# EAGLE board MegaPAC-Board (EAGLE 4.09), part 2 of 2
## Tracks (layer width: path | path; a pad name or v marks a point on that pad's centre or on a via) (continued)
S$583  (via drill 0.81 pad 1.78)
  other vias: 55.88,15.24
S$584  (via drill 0.81 pad 1.78)
  other vias: 55.88,12.7
S$585  (via drill 0.81 pad 1.78)
  other vias: 55.88,10.16
S$586
  Bottom 1.676: 62.87,25.72 45.4,25.72 45.4,40.01
S$587  (via drill 0.81 pad 1.78)
  other vias: 17.78,88.9
S$588  (via drill 0.81 pad 1.78)
  other vias: 53.34,10.16
S$589  (via drill 0.81 pad 1.78)
  other vias: 53.34,12.7
S$590  (via drill 0.81 pad 1.78)
  other vias: 53.34,15.24
S$591  (via drill 0.81 pad 1.78)
  other vias: 50.8,15.24
S$592  (via drill 0.81 pad 1.78)
  other vias: 50.8,12.7
S$593  (via drill 0.81 pad 1.78)
  other vias: 50.8,10.16
S$594  (via drill 0.81 pad 1.78)
  other vias: 50.8,7.62
S$595  (via drill 0.81 pad 1.78)
  other vias: 48.26,7.62
S$596  (via drill 0.81 pad 1.78)
  other vias: 48.26,10.16
S$597  (via drill 0.81 pad 1.78)
  other vias: 48.26,12.7
S$598  (via drill 0.81 pad 1.78)
  other vias: 48.26,15.24
S$599  (via drill 0.81 pad 1.78)
  other vias: 45.72,15.24
S$600  (via drill 0.81 pad 1.78)
  other vias: 45.72,12.7
S$601  (via drill 0.81 pad 1.78)
  other vias: 45.72,10.16
S$602  (via drill 0.81 pad 1.78)
  other vias: 45.72,7.62
S$603  (via drill 0.81 pad 1.78)
  other vias: 38.1,40.64
S$604  (via drill 0.81 pad 1.78)
  other vias: 38.1,38.1
S$605  (via drill 0.81 pad 1.78)
  other vias: 35.56,38.1
S$606  (via drill 0.81 pad 1.78)
  other vias: 33.02,38.1
S$607  (via drill 0.81 pad 1.78)
  other vias: 33.02,35.56
S$608  (via drill 0.81 pad 1.78)
  other vias: 35.56,35.56
S$609  (via drill 0.81 pad 1.78)
  other vias: 38.1,35.56
S$610  (via drill 0.81 pad 1.78)
  other vias: 38.1,33.02
S$611  (via drill 0.81 pad 1.78)
  other vias: 38.1,30.48
S$612  (via drill 0.81 pad 1.78)
  other vias: 38.1,27.94
S$613  (via drill 0.81 pad 1.78)
  other vias: 38.1,25.4
S$614  (via drill 0.81 pad 1.78)
  other vias: 35.56,25.4
S$615  (via drill 0.81 pad 1.78)
  other vias: 35.56,27.94
S$616  (via drill 0.81 pad 1.78)
  other vias: 35.56,30.48
S$617  (via drill 0.81 pad 1.78)
  other vias: 35.56,33.02
S$618  (via drill 0.81 pad 1.78)
  other vias: 33.02,33.02
S$619  (via drill 0.81 pad 1.78)
  other vias: 33.02,30.48
S$620  (via drill 0.81 pad 1.78)
  other vias: 33.02,27.94
S$621  (via drill 0.81 pad 1.78)
  other vias: 33.02,25.4
S$622  (via drill 0.81 pad 1.78)
  other vias: 33.02,22.86
S$623  (via drill 0.81 pad 1.78)
  other vias: 35.56,22.86
S$624  (via drill 0.81 pad 1.78)
  other vias: 38.1,22.86
S$625  (via drill 0.81 pad 1.78)
  other vias: 38.1,20.32
S$626  (via drill 0.81 pad 1.78)
  other vias: 35.56,20.32
S$627  (via drill 0.81 pad 1.78)
  other vias: 33.02,20.32
S$628  (via drill 0.81 pad 1.78)
  other vias: 33.02,17.78
S$629  (via drill 0.81 pad 1.78)
  other vias: 35.56,17.78
S$630  (via drill 0.81 pad 1.78)
  other vias: 38.1,17.78
S$631  (via drill 0.81 pad 1.78)
  other vias: 38.1,15.24
S$632  (via drill 0.81 pad 1.78)
  other vias: 38.1,12.7
S$633  (via drill 0.81 pad 1.78)
  other vias: 38.1,10.16
S$634  (via drill 0.81 pad 1.78)
  other vias: 38.1,7.62
S$635  (via drill 0.81 pad 1.78)
  other vias: 35.56,7.62
S$636  (via drill 0.81 pad 1.78)
  other vias: 35.56,10.16
S$637  (via drill 0.81 pad 1.78)
  other vias: 35.56,12.7
S$638  (via drill 0.81 pad 1.78)
  other vias: 35.56,15.24
S$639  (via drill 0.81 pad 1.78)
  other vias: 33.02,15.24
S$640  (via drill 0.81 pad 1.78)
  other vias: 33.02,12.7
S$641  (via drill 0.81 pad 1.78)
  other vias: 33.02,10.16
S$642  (via drill 0.81 pad 1.78)
  other vias: 33.02,7.62
S$643  (via drill 0.81 pad 1.78)
  other vias: 68.58,22.86
S$644  (via drill 0.81 pad 1.78)
  other vias: 71.12,22.86
S$645  (via drill 0.81 pad 1.78)
  other vias: 73.66,22.86
S$646  (via drill 0.81 pad 1.78)
  other vias: 73.66,20.32
S$647  (via drill 0.81 pad 1.78)
  other vias: 71.12,20.32
S$648  (via drill 0.81 pad 1.78)
  other vias: 68.58,20.32
S$649  (via drill 0.81 pad 1.78)
  other vias: 68.58,17.78
S$650  (via drill 0.81 pad 1.78)
  other vias: 71.12,17.78
S$651  (via drill 0.81 pad 1.78)
  other vias: 73.66,17.78
S$652  (via drill 0.81 pad 1.78)
  other vias: 73.66,15.24
S$653  (via drill 0.81 pad 1.78)
  other vias: 73.66,12.7
S$654  (via drill 0.81 pad 1.78)
  other vias: 73.66,10.16
S$655  (via drill 0.81 pad 1.78)
  other vias: 73.66,7.62
S$656  (via drill 0.81 pad 1.78)
  other vias: 71.12,7.62
S$658  (via drill 0.81 pad 1.78)
  other vias: 71.12,10.16
S$659  (via drill 0.81 pad 1.78)
  other vias: 71.12,12.7
S$660  (via drill 0.81 pad 1.78)
  other vias: 71.12,15.24
S$661  (via drill 0.81 pad 1.78)
  other vias: 68.58,15.24
S$662  (via drill 0.81 pad 1.78)
  other vias: 68.58,12.7
S$663  (via drill 0.81 pad 1.78)
  other vias: 68.58,10.16
S$664  (via drill 0.81 pad 1.78)
  other vias: 68.58,7.62
S$665  (via drill 0.81 pad 1.78)
  other vias: 139.7,22.86
S$666  (via drill 0.81 pad 1.78)
  other vias: 142.24,22.86
S$667  (via drill 0.81 pad 1.78)
  other vias: 144.78,22.86
S$668  (via drill 0.81 pad 1.78)
  other vias: 144.78,20.32
S$669  (via drill 0.81 pad 1.78)
  other vias: 142.24,20.32
S$670  (via drill 0.81 pad 1.78)
  other vias: 139.7,20.32
S$671  (via drill 0.81 pad 1.78)
  other vias: 139.7,17.78
S$672  (via drill 0.81 pad 1.78)
  other vias: 142.24,17.78
S$674  (via drill 0.81 pad 1.78)
  other vias: 144.78,17.78
S$675  (via drill 0.81 pad 1.78)
  other vias: 144.78,15.24
S$676  (via drill 0.81 pad 1.78)
  other vias: 144.78,12.7
S$677  (via drill 0.81 pad 1.78)
  other vias: 144.78,10.16
S$678
  Bottom 1.778: 132.08,17.78 134.62,17.78
S$679
  Bottom 1.778: 132.08,20.32 134.62,20.32
S$680  (via drill 0.81 pad 1.78)
  other vias: 142.24,10.16
S$681  (via drill 0.81 pad 1.78)
  other vias: 142.24,12.7
S$682  (via drill 0.81 pad 1.78)
  other vias: 142.24,15.24
S$683  (via drill 0.81 pad 1.78)
  other vias: 139.7,15.24
S$684  (via drill 0.81 pad 1.78)
  other vias: 139.7,12.7
S$685  (via drill 0.81 pad 1.78)
  other vias: 139.7,10.16
S$686
  Bottom 1.676: 21.59,39.37 K1.P$2
S$687  (via drill 0.81 pad 1.78)
  other vias: 147.32,22.86
S$688  (via drill 0.81 pad 1.78)
  other vias: 149.86,22.86
S$689  (via drill 0.81 pad 1.78)
  other vias: 152.4,22.86
S$690  (via drill 0.81 pad 1.78)
  other vias: 152.4,20.32
S$691  (via drill 0.81 pad 1.78)
  other vias: 149.86,20.32
S$692  (via drill 0.81 pad 1.78)
  other vias: 147.32,20.32
S$694  (via drill 0.81 pad 1.78)
  other vias: 147.32,17.78
S$695  (via drill 0.81 pad 1.78)
  other vias: 149.86,17.78
S$696  (via drill 0.81 pad 1.78)
  other vias: 152.4,17.78
S$697  (via drill 0.81 pad 1.78)
  other vias: 147.32,15.24
S$698  (via drill 0.81 pad 1.78)
  other vias: 149.86,15.24
S$699  (via drill 0.81 pad 1.78)
  other vias: 152.4,15.24
S$700  (via drill 0.81 pad 1.78)
  other vias: 154.94,22.86
S$701  (via drill 0.81 pad 1.78)
  other vias: 154.94,20.32
S$702  (via drill 0.81 pad 1.78)
  other vias: 154.94,17.78
S$703  (via drill 0.81 pad 1.78)
  other vias: 154.94,15.24
S$704
  Bottom 1.778: 132.08,15.24 134.62,15.24
S$705
  Bottom 2.54: 135.89,78.74 153.67,78.74
S$706
  Bottom 1.422: H5.K 120.65,93.03 120.65,90.17
  Bottom 1.676: H5.K 119.7,94.3 | 120.65,90.17 123.19,90.17 | 118.43,85.72 118.43,87.63
  Bottom 1.778: 131.44,80.01 131.44,89.22 | 132.72,79.38 132.72,89.85 128.59,89.85 | 120.02,90.17 120.65,90.17 117.47,90.17 117.47,87.63 118.43,87.63
  Bottom 1.93: 131.44,80.01 128.59,80.01 128.59,89.85 128.59,90.17 123.19,90.17 | 120.65,90.17 120.65,87.63 118.43,87.63
S$707
  Bottom 1.676: 135.89,80.01 135.89,80.33 | 135.89,80.01 135.89,79.38 | 135.89,80.01 135.57,80.33 136.21,80.33 136.21,79.69 135.57,79.69
S$709
  Bottom 1.676: 21.59,22.86 K2.P$2
S$710  (via drill 0.81 pad 1.78)  (4 unrouted)
  other vias: 142.24,5.08 139.7,5.08 139.7,2.54 142.24,2.54 144.78,2.54
S$711  (via drill 0.81 pad 1.78)
  other vias: 144.78,5.08
S$712  (via drill 0.81 pad 1.78)
  other vias: 129.54,22.86
S$713  (via drill 0.81 pad 1.78)
  other vias: 129.54,20.32
S$714  (via drill 0.81 pad 1.78)
  other vias: 129.54,17.78
S$715  (via drill 0.81 pad 1.78)
  other vias: 15.24,88.9
S$716  (via drill 0.81 pad 1.78)
  other vias: 12.7,88.9
S$717  (via drill 0.81 pad 1.78)
  other vias: 12.7,91.44
S$718  (via drill 0.81 pad 1.78)
  other vias: 15.24,91.44
S$719  (via drill 0.81 pad 1.78)
  other vias: 129.54,25.4
S$720  (via drill 0.81 pad 1.78)
  other vias: 127,25.4
S$721  (via drill 0.81 pad 1.78)
  other vias: 124.46,25.4
S$722  (via drill 0.81 pad 1.78)
  other vias: 121.92,25.4
S$723  (via drill 0.81 pad 1.78)
  other vias: 119.38,25.4
S$724  (via drill 0.81 pad 1.78)
  other vias: 116.84,25.4
S$725  (via drill 0.81 pad 1.78)
  other vias: 114.3,25.4
S$726  (via drill 0.81 pad 1.78)
  other vias: 111.76,25.4
S$727  (via drill 0.81 pad 1.78)
  other vias: 109.22,25.4
S$728  (via drill 0.81 pad 1.78)
  other vias: 106.68,25.4
S$729  (via drill 0.81 pad 1.78)
  other vias: 104.14,25.4
S$730  (via drill 0.81 pad 1.78)
  other vias: 101.6,25.4
S$731  (via drill 0.81 pad 1.78)
  other vias: 99.06,25.4
S$732  (via drill 0.81 pad 1.78)
  other vias: 96.52,25.4
S$733  (via drill 0.81 pad 1.78)
  other vias: 93.98,25.4
S$734  (via drill 0.81 pad 1.78)
  other vias: 91.44,25.4
S$735  (via drill 0.81 pad 1.78)
  other vias: 88.9,25.4
S$736  (via drill 0.81 pad 1.78)
  other vias: 86.36,25.4
S$737  (via drill 0.81 pad 1.78)
  other vias: 83.82,25.4
S$738  (via drill 0.81 pad 1.78)
  other vias: 68.58,5.08
S$739  (via drill 0.81 pad 1.78)
  other vias: 71.12,5.08
S$740  (via drill 0.81 pad 1.78)
  other vias: 73.66,5.08
S$741  (via drill 0.81 pad 1.78)
  other vias: 76.2,5.08
S$742  (via drill 0.81 pad 1.78)
  other vias: 78.74,5.08
S$743  (via drill 0.81 pad 1.78)
  other vias: 81.28,5.08
S$744  (via drill 0.81 pad 1.78)
  other vias: 83.82,5.08
S$745  (via drill 0.81 pad 1.78)
  other vias: 86.36,5.08
S$746  (via drill 0.81 pad 1.78)
  other vias: 88.9,5.08
S$747  (via drill 0.81 pad 1.78)
  other vias: 91.44,5.08
S$748  (via drill 0.81 pad 1.78)
  other vias: 93.98,5.08
S$749  (via drill 0.81 pad 1.78)
  other vias: 96.52,5.08
S$750  (via drill 0.81 pad 1.78)
  other vias: 99.06,5.08
S$751  (via drill 0.81 pad 1.78)
  other vias: 101.6,5.08
S$752  (via drill 0.81 pad 1.78)
  other vias: 104.14,5.08
S$753  (via drill 0.81 pad 1.78)
  other vias: 106.68,5.08
S$754  (via drill 0.81 pad 1.78)
  other vias: 109.22,5.08
S$755  (via drill 0.81 pad 1.78)
  other vias: 111.76,5.08
S$756  (via drill 0.81 pad 1.78)
  other vias: 114.3,5.08
S$757  (via drill 0.81 pad 1.78)
  other vias: 116.84,5.08
S$758  (via drill 0.81 pad 1.78)
  other vias: 119.38,5.08
S$759  (via drill 0.81 pad 1.78)
  other vias: 121.92,5.08
S$760  (via drill 0.81 pad 1.78)
  other vias: 124.46,5.08
S$761  (via drill 0.81 pad 1.78)
  other vias: 127,5.08
S$762  (via drill 0.81 pad 1.78)
  other vias: 17.78,91.44
S$763  (via drill 0.81 pad 1.78)
  other vias: 66.04,22.86
S$764  (via drill 0.81 pad 1.78)
  other vias: 66.04,20.32
S$765  (via drill 0.81 pad 1.78)
  other vias: 66.04,17.78
S$766  (via drill 0.81 pad 1.78)
  other vias: 66.04,15.24
S$767  (via drill 0.81 pad 1.78)
  other vias: 66.04,12.7
S$768  (via drill 0.81 pad 1.78)
  other vias: 66.04,10.16
S$769  (via drill 0.81 pad 1.78)
  other vias: 66.04,7.62
S$770  (via drill 0.81 pad 1.78)
  other vias: 66.04,5.08
S$771  (via drill 0.81 pad 1.78)
  other vias: 17.78,93.98
S$772  (via drill 0.81 pad 1.78)
  other vias: 15.24,93.98
S$773  (via drill 0.81 pad 1.78)
  other vias: 50.8,5.08
S$774  (via drill 0.81 pad 1.78)
  other vias: 48.26,5.08
S$775  (via drill 0.81 pad 1.78)
  other vias: 45.72,5.08
S$776  (via drill 0.81 pad 1.78)
  other vias: 43.18,5.08
S$777  (via drill 0.81 pad 1.78)
  other vias: 43.18,7.62
S$778  (via drill 0.81 pad 1.78)
  other vias: 43.18,10.16
S$779  (via drill 0.81 pad 1.78)
  other vias: 43.18,12.7
S$780  (via drill 0.81 pad 1.78)
  other vias: 43.18,15.24
S$781  (via drill 0.81 pad 1.78)
  other vias: 43.18,17.78
S$782  (via drill 0.81 pad 1.78)
  other vias: 43.18,20.32
S$783  (via drill 0.81 pad 1.78)
  other vias: 43.18,22.86
S$784  (via drill 0.81 pad 1.78)
  other vias: 40.64,22.86
S$785  (via drill 0.81 pad 1.78)
  other vias: 40.64,20.32
S$786  (via drill 0.81 pad 1.78)
  other vias: 40.64,17.78
S$787  (via drill 0.81 pad 1.78)
  other vias: 40.64,15.24
S$788  (via drill 0.81 pad 1.78)
  other vias: 40.64,12.7
S$789  (via drill 0.81 pad 1.78)
  other vias: 40.64,10.16
S$790  (via drill 0.81 pad 1.78)
  other vias: 40.64,7.62
S$791  (via drill 0.81 pad 1.78)
  other vias: 40.64,5.08
S$792  (via drill 0.81 pad 1.78)
  other vias: 38.1,5.08
S$793  (via drill 0.81 pad 1.78)
  other vias: 35.56,5.08
S$794  (via drill 0.81 pad 1.78)
  other vias: 33.02,5.08
S$795  (via drill 0.81 pad 1.78)
  other vias: 12.7,93.98
S$796  (via drill 0.81 pad 1.78)
  other vias: 12.7,96.52
S$797  (via drill 0.81 pad 1.78)
  other vias: 15.24,96.52
S$798  (via drill 0.81 pad 1.78)
  other vias: 17.78,96.52
S$799  (via drill 0.81 pad 1.78)
  other vias: 17.78,50.8
S$800  (via drill 0.81 pad 1.78)
  other vias: 15.24,50.8
S$801  (via drill 0.81 pad 1.78)
  other vias: 12.7,50.8
S$802  (via drill 0.81 pad 1.78)
  other vias: 10.16,50.8
S$803  (via drill 0.81 pad 1.78)
  other vias: 7.62,50.8
S$804  (via drill 0.81 pad 1.78)
  other vias: 5.08,50.8
S$805  (via drill 0.81 pad 1.78)
  other vias: 2.54,50.8
S$806  (via drill 0.81 pad 1.78)
  other vias: 2.54,48.26
S$807  (via drill 0.81 pad 1.78)
  other vias: 5.08,48.26
S$808  (via drill 0.81 pad 1.78)
  other vias: 7.62,48.26
S$809  (via drill 0.81 pad 1.78)
  other vias: 10.16,48.26
S$810  (via drill 0.81 pad 1.78)
  other vias: 12.7,48.26
S$811  (via drill 0.81 pad 1.78)
  other vias: 15.24,48.26
S$812  (via drill 0.81 pad 1.78)
  other vias: 17.78,48.26
S$813  (via drill 0.81 pad 1.78)
  other vias: 17.78,45.72
S$814  (via drill 0.81 pad 1.78)
  other vias: 15.24,45.72
S$815  (via drill 0.81 pad 1.78)
  other vias: 12.7,45.72
S$816  (via drill 0.81 pad 1.78)
  other vias: 10.16,45.72
S$817  (via drill 0.81 pad 1.78)
  other vias: 7.62,45.72
S$818  (via drill 0.81 pad 1.78)
  other vias: 5.08,45.72
S$819  (via drill 0.81 pad 1.78)
  other vias: 2.54,45.72
S$820  (via drill 0.81 pad 1.78)
  other vias: 30.48,40.64
S$821  (via drill 0.81 pad 1.78)
  other vias: 30.48,33.02
S$822  (via drill 0.81 pad 1.78)
  other vias: 30.8,22.86
S$823  (via drill 0.81 pad 1.78)
  other vias: 30.8,15.24
S$824  (via drill 0.81 pad 1.78)
  other vias: 40.64,40.64
S$825  (via drill 0.81 pad 1.78)
  other vias: 40.64,43.18
S$826  (via drill 0.81 pad 1.78)
  other vias: 40.64,45.72
S$827  (via drill 0.81 pad 1.78)
  other vias: 40.64,48.26
S$828  (via drill 0.81 pad 1.78)
  other vias: 40.64,50.8
S$829  (via drill 0.81 pad 1.78)
  other vias: 40.64,53.34
S$830  (via drill 0.81 pad 1.78)
  other vias: 40.64,55.88
S$831  (via drill 0.81 pad 1.78)
  other vias: 40.64,58.42
S$832  (via drill 0.81 pad 1.78)
  other vias: 40.64,60.96
S$833  (via drill 0.81 pad 1.78)
  other vias: 40.64,63.5
S$834  (via drill 0.81 pad 1.78)
  other vias: 40.64,66.04
S$835  (via drill 0.81 pad 1.78)
  other vias: 40.64,68.58
S$836  (via drill 0.81 pad 1.78)
  other vias: 40.64,71.12
S$837  (via drill 0.81 pad 1.78)
  other vias: 40.64,73.66
S$838  (via drill 0.81 pad 1.78)
  other vias: 40.64,76.2
S$839  (via drill 0.81 pad 1.78)
  other vias: 43.18,76.2
S$840  (via drill 0.81 pad 1.78)
  other vias: 45.72,76.2
S$841  (via drill 0.81 pad 1.78)
  other vias: 43.18,73.66
S$842  (via drill 0.81 pad 1.78)
  other vias: 43.18,71.12
S$843  (via drill 0.81 pad 1.78)
  other vias: 48.26,86.36
S$844  (via drill 0.81 pad 1.78)
  other vias: 50.8,86.36
S$845
  Bottom 1.016: 139.06,34.92 139.06,34.29 | 139.06,34.92 139.06,36.51 | 139.06,34.92 140.65,36.83
S$846  (via drill 0.81 pad 1.78)
  other vias: 40.64,38.1
S$847  (via drill 0.81 pad 1.78)
  other vias: 40.64,35.56
S$848  (via drill 0.81 pad 1.78)
  other vias: 40.64,33.02
S$849  (via drill 0.81 pad 1.78)
  other vias: 40.64,30.48
S$850  (via drill 0.81 pad 1.78)
  other vias: 40.64,27.94
S$851  (via drill 0.81 pad 1.78)
  other vias: 40.64,25.4
S$852  (via drill 0.81 pad 1.78)
  other vias: 43.18,38.1
S$853  (via drill 0.81 pad 1.78)
  other vias: 43.18,35.56
S$854  (via drill 0.81 pad 1.78)
  other vias: 43.18,33.02
S$855  (via drill 0.81 pad 1.78)
  other vias: 43.18,30.48
S$856  (via drill 0.81 pad 1.78)
  other vias: 43.18,27.94
S$857  (via drill 0.81 pad 1.78)
  other vias: 43.18,25.4
S$858  (via drill 0.81 pad 1.78)
  other vias: 30.48,10.16
S$859  (via drill 0.81 pad 1.78)
  other vias: 30.48,7.62
S$860  (via drill 0.81 pad 1.78)
  other vias: 30.48,5.08
S$861  (via drill 0.81 pad 1.78)
  other vias: 27.94,5.08
S$862  (via drill 0.81 pad 1.78)
  other vias: 27.94,7.62
S$863  (via drill 0.81 pad 1.78)
  other vias: 27.94,10.16
S$864  (via drill 0.81 pad 1.78)
  other vias: 25.4,10.16
S$865  (via drill 0.81 pad 1.78)
  other vias: 25.4,7.62
S$866  (via drill 0.81 pad 1.78)
  other vias: 25.4,5.08
S$867  (via drill 0.81 pad 1.78)
  other vias: 15.24,10.16
S$868  (via drill 0.81 pad 1.78)
  other vias: 15.24,7.62
S$869  (via drill 0.81 pad 1.78)
  other vias: 15.24,5.08
S$870  (via drill 0.81 pad 1.78)
  other vias: 12.7,5.08
S$871  (via drill 0.81 pad 1.78)
  other vias: 12.7,7.62
S$872  (via drill 0.81 pad 1.78)
  other vias: 12.7,10.16
S$873  (via drill 0.81 pad 1.78)
  other vias: 17.78,10.16
S$874  (via drill 0.81 pad 1.78)
  other vias: 17.78,7.62
S$875  (via drill 0.81 pad 1.78)
  other vias: 17.78,5.08
S$876  (via drill 0.81 pad 1.78)
  other vias: 22.86,5.08
S$877  (via drill 0.81 pad 1.78)
  other vias: 22.86,7.62
S$878  (via drill 0.81 pad 1.78)
  other vias: 22.86,10.16
S$879
  Bottom 1.016: 139.7,36.2 139.7,35.88
S$880
  Bottom 1.676: LCD.P$18 109.22,33.97
S$881
  Bottom 1.676: 119.06,34.29 119.7,34.29
S$882
  Bottom 1.676: 119.06,31.75 119.7,31.75
S$883
  Bottom 1.676: 121.92,32.07 LCD.P$31 122.56,31.75
S$884
  Bottom 1.676: LCD.P$23 122.56,34.29
S$885
  Bottom 1.676: 125.41,31.75 124.78,31.75
S$886
  Bottom 1.676: 125.41,34.29 125.09,34.29
S$887
  Bottom 1.676: 108.9,31.75 109.54,31.75
S$888
  Bottom 1.676: 111.44,34.29 112.08,34.29
S$889
  Bottom 1.778: 123.83,93.98 133.03,93.98
  Bottom 1.93: 123.83,92.71 123.83,93.98
S$890
  Bottom 1.778: 123.51,92.71 133.03,92.71 133.03,97.79
S$891
  Bottom 1.778: 131.44,94.3 131.44,97.16
S$892
  Bottom 1.778: 144.78,93.98 144.78,97.79 103.82,97.79
  Bottom 2.54: 144.78,92.71 144.78,93.98 144.78,95.25
S$893
  Bottom 1.676: 136.53,95.25 137.48,95.25
  Bottom 1.778: 136.53,95.25 136.53,90.81 137.48,90.81 137.48,95.25
S$894
  Bottom 1.676: 144.46,91.76 146.37,91.76 146.37,97.79 145.1,97.79
  Bottom 1.778: 144.78,92.39 144.46,91.76 144.46,96.52
S$895
  Bottom 1.778: 135.57,84.14 135.57,86.04 142.56,86.04 | 142.56,86.04 144.46,86.04 | 142.56,86.04 154.94,86.04 154.94,83.5 154.31,83.5
S$896
  Bottom 1.676: 128.27,78.42 128.27,76.52 128.59,76.2 153.35,76.2
  Bottom 1.778: 135.89,78.42 128.27,78.42 128.27,89.85
S$897
  Bottom 1.778: 130.18,80.64 130.18,88.9
S$898
  Bottom 1.778: 118.43,88.9 119.7,88.9
S$899
  Bottom 0.406: 105.09,80.64 103.19,80.64 103.19,85.09 105.41,85.09
  Bottom 1.676: 104.78,85.09 105.41,85.09 111.76,85.09 R19.2
S$900
  Bottom 1.676: 88.9,49.21 90.17,50.48
S$901
  Bottom 1.016: 49.53,34.29 48.26,34.29 48.26,38.1 51.44,38.1 51.44,34.61
S$902
  Bottom 1.016: 62.55,26.99 62.55,31.43
S$903
  Bottom 1.016: 70.48,25.72 70.48,26.99 78.42,26.99
S$904
  Bottom 1.016: 71.12,26.99 78.42,26.99
S$905
  Bottom 1.016: 71.12,26.04 78.11,26.04
S$906
  Bottom 1.016: 72.07,39.69 72.07,41.59
S$907
  Bottom 1.016: 71.44,42.23 71.44,39.69 72.71,39.05 73.34,39.05 74.3,39.69 74.3,42.23 73.03,42.23
S$908
  Bottom 1.676: 120.02,90.81 120.02,93.34
S$909
  Bottom 1.676: 129.54,77.15 153.35,77.15
S$910
  Bottom 1.676: 146.37,73.03 146.37,75.56
S$911
  Bottom 0.254: 101.6,44.45 95.57,44.45 | JMP7.P$3 85.72,43.18 87.63,43.18 | 87.63,43.18 87.63,40.01 | JMP6.P$3 85.72,46.99 87.63,46.99 | 87.63,46.99 87.63,43.18 | 87.63,51.44 87.63,46.99 | 75.88,55.24 81.28,55.24 | 69.85,25.08 69.85,39.05
  Bottom 0.305: 113.67,64.77 101.92,64.77 | 101.6,67.31 111.44,67.31 | 95.57,44.45 95.25,44.45 | 101.6,45.09 101.6,44.45 101.6,43.18 101.6,42.55 100.65,41.91 95.25,41.91 91.12,38.42 89.22,37.78 76.52,37.78 75.56,37.47 73.66,36.2 73.66,35.88 | 83.5,51.44 87.63,51.44 | 75.88,55.24 74.93,55.88 68.9,55.88
  Bottom 0.406: 113.67,64.77 117.16,63.18 118.75,63.18 | T1.P$3 118.75,70.8 115.89,70.8 114.3,70.17 111.44,67.31 | 95.57,44.45 94.93,44.45 89.53,40.01 87.63,40.01
  Bottom 0.61: 133.67,37.47 133.67,40.01 135.25,41.27 140.34,41.27 141.6,43.81 141.6,44.13 | 92.39,79.69 86.68,79.69 86.36,79.38 86.36,78.74 | 76.2,81.28 76.2,78.74 67.63,78.74 67.63,68.26 73.34,68.26 | 69.85,39.05 68.9,40.64 | 19.68,2.22 19.68,98.11
  Bottom 0.813: 68.58,42.55 61.91,42.55 59.05,39.69 46.35,39.69 46.35,30.48
  Bottom 1.016: 139.7,44.13 138.75,44.13 138.75,53.66 | 68.9,63.5 68.9,55.88 68.9,40.64
  Bottom 1.27: 86.36,78.74 91.44,78.74 IC3.4 | IC2.8 72.39,62.55 72.39,63.5 68.9,63.5 | 73.66,35.24 73.66,35.88 | 63.5,26.67 63.5,33.66
  Bottom 1.422: 118.75,62.87 132.72,62.87 146.69,62.87 154.94,62.87 | X1.1 154.62,80.01 154.94,80.01 154.94,62.87 | 93.98,63.5 94.61,63.5 | 93.98,63.5 93.34,63.5 | 154.94,58.1 154.94,62.87 | 93.98,63.5 93.03,63.5 90.17,62.55 | 54.93,40.01 45.72,40.01 45.72,32.07
  Bottom 1.676: 121.6,54.93 123.19,54.93 123.19,53.34 | 123.19,53.34 123.19,48.58 | 123.19,53.34 R3.A 121.6,52.7 121.6,55.24 120.02,56.52 116.2,56.52 C7.1 113.67,59.69 112.08,60.96 107.95,60.96 | 141.6,43.81 139.06,43.81 | 77.79,80.96 77.79,79.38 74.3,79.38 74.3,81.28 XC.P$5 76.2,81.28 XC.P$11 | 139.7,44.13 141.6,44.13 | 101.6,82.55 IC3.4 | T2.P$3 132.72,70.8 | 138.75,53.66 138.75,55.24 140.97,57.15 140.97,58.1 | 153.35,61.91 146.69,61.91 140.97,61.91 | 84.14,41.59 JMP7.P$3 82.23,41.59 | 82.23,45.4 JMP6.P$3 84.14,45.4 | 140.97,61.91 132.08,61.91 | 140.97,58.1 140.97,61.91 | 100.01,58.42 101.6,60.01 | 101.6,43.18 101.6,45.09 | 140.97,58.1 146.05,58.1 154.94,58.1 154.94,31.75 147.96,31.75 147.96,26.35 157.16,26.35 157.16,13.34 | 73.34,67.94 73.34,63.82 | 73.34,67.94 73.34,72.71 76.52,72.71 76.52,68.26 | 93.34,58.42 90.17,58.42 90.17,62.55 82.55,62.55 82.55,60.33 | JMP5.P$3 83.82,51.44 83.5,51.44 78.74,51.44 | 73.34,67.94 73.34,68.26 76.52,68.26 | 78.74,51.44 78.11,51.44 | 78.74,51.44 79.38,51.44 81.28,52.7 81.28,55.24 81.28,60.33 82.55,60.33 | 82.55,60.33 82.55,59.69 | 76.52,68.26 76.52,66.04 73.03,62.55 72.39,62.55 | 156.21,25.4 156.21,13.34 156.53,13.34 | 68.58,42.55 68.58,51.44 | 86.36,32.7 LCD.P$10 83.82,34.29 | 83.82,34.29 83.82,32.7 | 83.82,34.29 83.82,35.24 | 81.28,34.29 83.82,34.29 | 81.28,34.29 81.28,32.7 | 78.74,34.29 78.74,34.92 | 78.74,34.29 81.28,34.29 | 78.74,34.29 78.74,35.24 | 46.99,31.75 46.35,30.48 46.35,26.67 48.26,26.67 | 78.74,29.21 78.74,34.29 | 78.74,29.21 87,29.21 | 78.74,29.21 78.74,25.08 73.66,25.08 | 73.66,34.61 73.66,34.92 | 73.66,34.61 73.66,35.24 | 48.26,26.67 48.26,32.07 45.72,32.07 45.72,26.67 48.26,26.67
  Bottom 1.676: 63.5,33.66 63.5,34.92 | 73.66,25.08 73.66,34.61 | 73.66,25.08 69.85,25.08 63.5,25.08 | 48.26,26.67 63.5,26.67 63.5,25.08 | 129.22,7.62 129.22,1.59 63.5,1.59 63.5,7.94 | 63.5,7.94 63.5,25.08 | 63.5,7.94 53.02,7.94 53.02,2.22 19.68,2.22 | 154.62,80.01 149.86,80.01
  Bottom 1.778: 108.58,60.96 107.95,60.96 102.87,60.96 100.97,58.42 100.01,58.42 93.34,58.42 | 156.53,13.34 157.16,13.34 157.16,12.38 152.4,12.38 148.59,10.79 147,7.62 | 155.89,12.7 147,12.7 147,7.62 | 146.37,8.57 129.54,8.57 129.22,7.62 147,7.62 | 129.86,6.67 129.86,1.59 129.22,1.59
  Bottom 1.93: 97.16,87.63 IC3.2 101.6,87.63 | 101.6,87.63 106.05,87.63 | 101.6,87.63 101.6,82.55 101.6,67.31 101.6,60.01 101.6,59.69 | 144.78,76.83 144.78,73.66 146.69,72.39 T3.P$3 146.69,62.87 | T1.P$3 118.75,63.18 118.75,62.87 | 146.05,57.78 148.27,57.78 148.27,58.74 146.05,58.74 146.05,58.1 | 146.69,61.91 146.69,59.37 | 101.6,59.69 101.6,59.05 | 101.6,45.09 101.6,59.69 | 132.72,62.87 T2.P$3
  Bottom 2.54: 144.78,76.83 D1.A 144.78,78.42
S$912
  Bottom 0.406: 123.19,49.85 123.19,50.16 123.51,50.16
S$913
  Bottom 1.676: 105.09,80.33 105.41,80.33 105.41,76.52
S$914
  Bottom 1.676: 130.81,49.85 132.08,49.85
S$915
  Bottom 1.676: 118.43,52.7 117.79,53.34
S$916
  Bottom 1.016: 140.34,41.91 140.34,42.86
S$917
  Bottom 0.254: 85.41,77.47 93.03,77.47
  Bottom 0.305: 93.03,77.47 93.66,78.11 | 93.98,85.09 93.98,84.14
  Bottom 0.61: 97.79,60.96 99.69,60.96 99.69,78.11 93.66,78.11 | 84.45,78.11 85.41,77.47
  Bottom 0.813: 84.45,78.11 84.45,79.38 86.04,81.6 91.12,81.6 93.98,83.5 93.98,84.14
  Bottom 1.016: 101.28,92.39 101.28,96.52 82.87,96.52 | 82.87,96.52 82.87,84.77 | 82.87,96.52 69.53,96.52 69.53,95.89
  Bottom 1.27: 111.44,88.27 108.27,88.27 108.27,90.17
  Bottom 1.422: 98.42,60.96 97.79,60.96 93.34,60.96 | 114.3,83.82 114.3,83.5 | 114.3,83.5 118.43,83.5 | 114.3,83.5 R1.1 | 55.88,88.9 55.88,87.63 60.64,87.63
  Bottom 1.676: 61.28,79.06 61.28,88.9 | 61.28,88.9 68.26,94.61 69.53,94.61 | 101.28,91.76 101.28,90.17 101.6,90.17 | 101.6,90.17 101.6,92.08 | 105.73,90.17 101.6,90.17 | 105.41,90.17 103.82,92.39 101.28,92.39 93.98,92.39 93.98,85.09 93.98,85.41 | 82.87,84.77 82.87,83.82 | R19.1 111.76,88.27 114.3,87 114.3,83.82 | 119.38,80.01 R1.1 114.3,76.83 125.09,76.83 | 125.09,76.83 L1.1 | 125.09,76.83 125.09,87 | 69.53,94.61 69.53,95.89 | 69.53,94.61 69.53,93.66 | 61.28,88.9 55.88,88.9 55.56,88.9
  Bottom 1.778: R1.1 124.78,80.01
  Bottom 1.93: R19.1 108.27,90.17 105.73,90.17 105.41,90.17 104.78,90.17 | 125.73,87.63 124.46,87.63 124.46,82.87 119.38,82.87 | 119.38,82.87 119.06,82.87 | 119.38,82.87 119.38,80.01 119.38,77.47
S$918
  Bottom 1.27: 108.58,88.9 111.12,88.9
S$919
  Bottom 1.676: 96.84,81.28 100.97,81.28
S$920
  Bottom 1.676: 94.61,80.33 100.97,80.33
S$921
  Bottom 0.813: 137.16,28.57 138.11,29.21
  Bottom 1.016: 99.06,33.02 99.06,28.57 137.16,28.57
  Bottom 1.422: 138.11,29.21 139.38,29.21
  Bottom 1.676: 99.06,33.02 LCD.P$15
S$923
  Bottom 1.422: 47.31,97.16 46.35,97.16

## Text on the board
Bottom: SF05/03
tPlace: Serial Comm. | +Vb | K | +Vc | POWER | +5V | +Vb | K | GND | K | RESET | K | +5V | C3 | K | ADC0 Voltg | Program | SCHRACK | SCHRACK | LCD Contrast | SF 05/03 | 1x16 char.
tOrigins: N1 | (optional) | C1 | (optional) | (optional) | (LC Backlight) | (optional)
